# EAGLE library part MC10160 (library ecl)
12-bin Parity Generator-checker
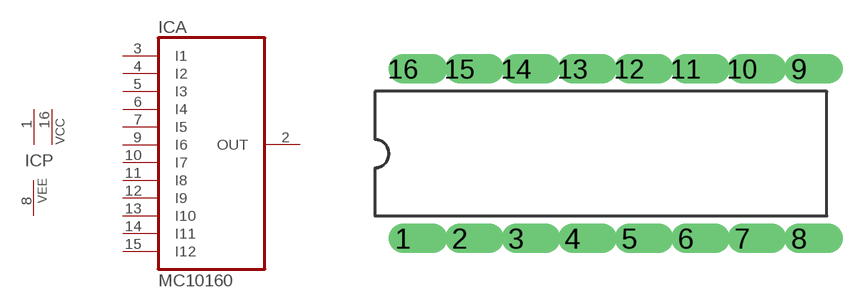
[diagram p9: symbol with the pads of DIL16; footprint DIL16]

Designator prefix IC; gates A=MC10160 P=2VCC1VEE

## MC10160  [DIL16]
1  P:VCC  pwr
2  A:OUT  out
3  A:I1  in
4  A:I2  in
5  A:I3  in
6  A:I4  in
7  A:I5  in
8  P:VEE  pwr
9  A:I6  in
10  A:I7  in
11  A:I8  in
12  A:I9  in
13  A:I10  in
14  A:I11  in
15  A:I12  in
16  P:VCC  pwr

## Footprint DIL16 (pad centres in mm)
drill 0.813 offset: 1 -8.89,-3.81; 2 -6.35,-3.81; 3 -3.81,-3.81; 4 -1.27,-3.81; 5 1.27,-3.81; 6 3.81,-3.81; 7 6.35,-3.81; 8 8.89,-3.81; 9 8.89,3.81; 10 6.35,3.81; 11 3.81,3.81; 12 1.27,3.81; 13 -1.27,3.81; 14 -3.81,3.81; 15 -6.35,3.81; 16 -8.89,3.81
